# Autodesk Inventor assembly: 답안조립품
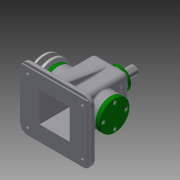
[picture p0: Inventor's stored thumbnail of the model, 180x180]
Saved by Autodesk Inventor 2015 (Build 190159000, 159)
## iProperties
Created: 2016-02
Part Number: 답안조립품
Document SubType Name: Assembly
Designer: Administrator
Author: Administrator
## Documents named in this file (18)
- C:\Users\Administrator\Desktop\460219V1003\답안조립품.iam
- C:\Users\Administrator\Desktop\460219V1003\본체.ipt
- C:\Users\Administrator\Desktop\460219V1003\뒤커버.ipt
- C:\Users\Administrator\Desktop\460219V1003\V-벨트풀리.ipt
- C:\Users\Administrator\Desktop\460219V1003\편심축.ipt
- C:\Users\Administrator\Desktop\460219V1003\키 5 x 5 x 14.ipt
- C:\Users\Administrator\Desktop\460219V1003\링크.ipt
- C:\Users\Administrator\Desktop\460219V1003\상부부시.ipt
- C:\Users\Administrator\Desktop\460219V1003\베어링 15 x 35 x 11.ipt
- C:\Users\Administrator\Desktop\460219V1003\앞커버.ipt
- C:\Users\Administrator\Desktop\460219V1003\와셔.ipt
- C:\Users\Administrator\Desktop\460219V1003\볼트 M6 x 12.ipt
- C:\Users\Administrator\Desktop\460219V1003\고정핀.ipt
- C:\Users\Administrator\Desktop\460219V1003\멈춤링 6 x 5.ipt
- C:\Users\Administrator\Desktop\460219V1003\슬라이드바.ipt
- C:\Users\Administrator\Desktop\460219V1003\멈춤링 15 x 1.ipt
- C:\Users\Administrator\Desktop\460219V1003\볼트 M4 x 10.ipt
- C:\Users\Administrator\Desktop\460219V1003\볼트 M3 x 8.ipt
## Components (15 placed, 5 different names)
1. V-벨트풀리:1
2. ISO 4018 M6 x 12:1
3. 고정핀:1
4. ISO 4762 M4 x 10:1
5. ISO 4762 M4 x 10:2
6. ISO 4762 M4 x 10:3
7. ISO 4762 M4 x 10:4
8. ISO 4762 M4 x 10:5
9. ISO 4762 M4 x 10:6
10. ISO 4762 M4 x 10:7
11. ISO 4762 M4 x 10:8
12. ISO 4762 M3 x 8:1
13. ISO 4762 M3 x 8:2
14. ISO 4762 M3 x 8:3
15. ISO 4762 M3 x 8:4
